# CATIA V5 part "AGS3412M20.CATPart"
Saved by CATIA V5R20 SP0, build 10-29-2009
Part number: AGS3412M20
Definition: NONE
Nomenclature: AGS3412M20
Source: Unknown
Description: AGS3412M20
Bounding box of the stored display mesh (mm): x -33 to 35, y -32.5 to 32.5, z -32.5 to 32.5
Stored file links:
  C:\Users\Utente\Desktop\IO LAVORO\3D X SITO CF\X SITO\PLASTICA\AGS\AGS3412M20.CATPart
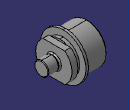
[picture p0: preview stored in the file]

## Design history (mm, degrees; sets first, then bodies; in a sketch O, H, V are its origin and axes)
Body1 "AGS3412M20" (main body)
  Solid1: solid without history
